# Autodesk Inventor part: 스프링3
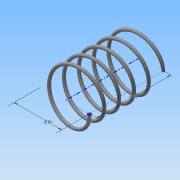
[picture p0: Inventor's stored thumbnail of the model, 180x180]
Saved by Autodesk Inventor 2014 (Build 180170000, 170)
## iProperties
Created: 2015-06
Part Number: 스프링3
Material: 강철, 연강
Document SubType Name: Modeling
Designer: MYHOME
Density: 1 g/cm^3
Appearance: 강철
Author: MYHOME
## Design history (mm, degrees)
sketch "스케치1"
  geometry: L1 (0, 0)-(8, 0); L2 (8, 0)-(8, 21.5); L3 (8, 21.5)-(0, 21.5); L4 (0, 21.5)-(0, 0); C1 r 0.5 at (8, 0)
  constraints: 8 end point, 2 parallel, 1 centre point, 1 coincident, 1 horizontal, 1 perpendicular
  dimensions: "d0" = 16 diameter of L2 L4; "d1" = 21.5 distance of L1.end L2.end (derived); "d2" = 1 diameter of C1
feature "코일2" sketch "스케치1" pitch "d17" = 10; turns "d19" = 5; dims "d18" = 21.5 (= d1), "d20" = 0, angle "d21" = 90 deg, angle "d22" = 90 deg, "d23" = 0, "d24" = 0
node "작업 평면3"
sketch "스케치4"
  geometry: L1 (-8.5, 0)-(-7.5, 0) reference; 1 further point
  constraints: 1 horizontal alignment
extrude "돌출3" cut sketch "스케치4" stored distance "d26" = 10; taper "d27" = 0 deg
node "작업 평면4"
sketch "스케치5"
  geometry: L1 (-7.5, 0)-(-8.5, 0) reference; 1 further point
  constraints: 1 horizontal alignment
extrude "돌출4" cut sketch "스케치5" stored distance "d29" = 10; taper "d30" = 0 deg
node "솔리드2"
node "절단 모서리 투영3"
node "절단 모서리 투영4"
other parameters: "d25" = 0, "d28" = 21.5 (= d1)
